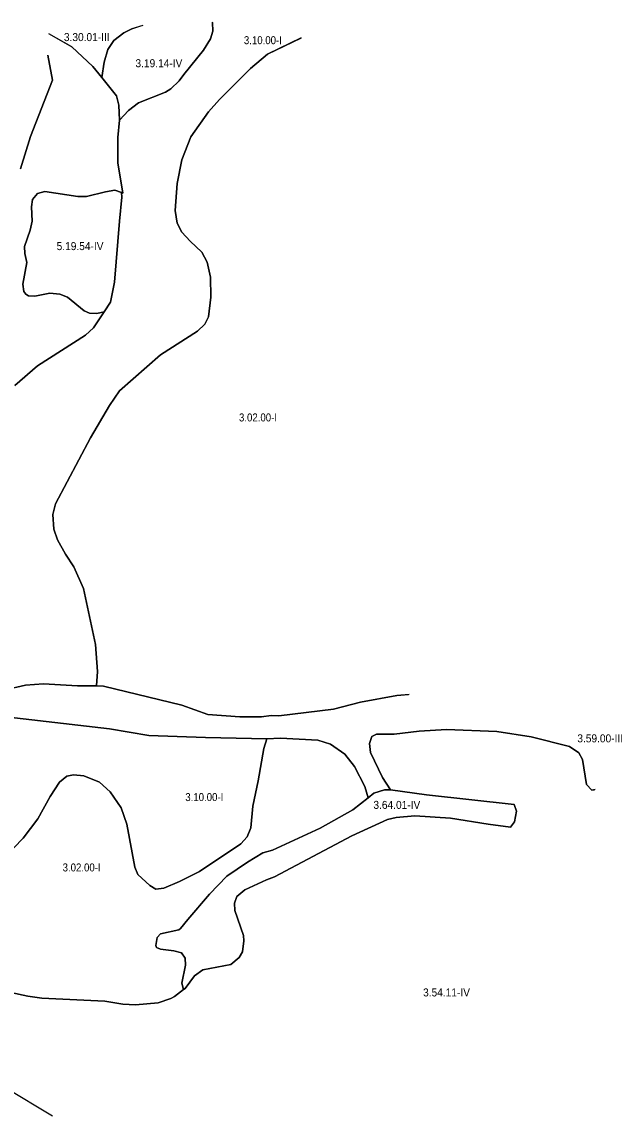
# Model space of a CAD drawing. Extents: x -589769 to -586623, y -1119592 to -1116833.
# Drawn here: x -588124 to -586623, y -1119592 to -1116859 of the extents above; entities that cross this region are included whole.
import ezdxf

# ---------------------------------------------------------------- set-up
doc = ezdxf.new("R2010")
doc.units = 0
doc.header["$LTSCALE"] = 8
doc.layers.add('40', color=7, linetype='Continuous', lineweight=25)
doc.layers.add('41', color=7, linetype='Continuous')

msp = doc.modelspace()

# ---------------------------------------------------------------- linework, layer by layer
at = {"layer": '40'}
for points in [[(-588141.5, -1117767), (-588085, -1117718), (-587964.5, -1117641.5), (-587944.5, -1117623.5), (-587918, -1117583), (-587902, -1117559), (-587892, -1117509.5), (-587880, -1117356.5), (-587873.5, -1117296.5), (-587875, -1117285.5), (-587871, -1117287), (-587883.5, -1117211), (-587883.5, -1117148), (-587880, -1117104.5), (-587857.5, -1117080), (-587832.5, -1117061), (-587765, -1117034.5), (-587751, -1117026), (-587730.5, -1117006), (-587719, -1116990.5), (-587669.5, -1116930), (-587652, -1116901), (-587646.5, -1116882), (-587647, -1116860.5)], [(-587648.116, -1116859.024), (-587647, -1116860.5), (-587646.5, -1116882), (-587652, -1116901), (-587669.5, -1116930), (-587719, -1116990.5), (-587730.5, -1117006), (-587751, -1117026), (-587765, -1117034.5), (-587832.5, -1117061), (-587857.5, -1117080), (-587880, -1117104.5), (-587881.5, -1117067), (-587887.5, -1117044), (-587924, -1116998), (-587918, -1116959.5), (-587909, -1116928), (-587894, -1116905.5), (-587868.5, -1116886), (-587849, -1116876.5), (-587828.645, -1116870.046)], [(-587821.559, -1116867.799), (-587849, -1116876.5), (-587868.5, -1116886), (-587894, -1116905.5), (-587909, -1116928), (-587918, -1116959.5), (-587924, -1116998), (-587946, -1116970.5), (-587998.5, -1116921), (-588056.201, -1116888.755)], [(-588055.306, -1116889.256), (-587998.5, -1116921), (-587946, -1116970.5), (-587924, -1116998)], [(-587425.916, -1116899.018), (-587510, -1116940), (-587552, -1116975.5), (-587629.5, -1117052.5), (-587657.5, -1117083.5), (-587701, -1117146), (-587723.5, -1117204), (-587735.5, -1117263), (-587740.5, -1117330.5), (-587735.5, -1117362), (-587724, -1117384.5), (-587703, -1117407), (-587673.5, -1117434), (-587660.5, -1117459), (-587652.5, -1117497), (-587651.5, -1117546.5), (-587657.5, -1117596), (-587666, -1117614), (-587684.5, -1117632), (-587777, -1117690.5), (-587880, -1117780.5), (-587904.5, -1117817), (-587952.5, -1117898), (-588040, -1118063), (-588046, -1118090), (-588043.5, -1118126), (-588034.5, -1118153), (-588015, -1118189)], [(-588040, -1118063), (-587952.5, -1117898), (-587904.5, -1117817), (-587880, -1117780.5), (-587777, -1117690.5), (-587684.5, -1117632), (-587666, -1117614), (-587657.5, -1117596), (-587651.5, -1117546.5), (-587652.5, -1117497), (-587660.5, -1117459), (-587673.5, -1117434), (-587703, -1117407), (-587724, -1117384.5), (-587735.5, -1117362), (-587740.5, -1117330.5), (-587735.5, -1117263), (-587723.5, -1117204), (-587701, -1117146), (-587657.5, -1117083.5), (-587629.5, -1117052.5), (-587552, -1116975.5), (-587510, -1116940), (-587425.003, -1116898.573)], [(-588058.91, -1116941.996), (-588047.5, -1117005), (-588102.5, -1117145.5), (-588127.5, -1117226.5)], [(-588127.5, -1117226.5), (-588102.5, -1117145.5), (-588047.5, -1117005), (-588058.91, -1116941.996), (-588058.91, -1116941.996)], [(-587924, -1116998), (-587887.5, -1117044), (-587881.5, -1117067), (-587880, -1117104.5), (-587883.5, -1117148), (-587883.5, -1117211), (-587871, -1117287), (-587875, -1117285.5), (-587891, -1117279.5), (-587915, -1117283.5), (-587962.5, -1117295.5), (-587983.5, -1117295.5), (-588066, -1117283), (-588084.5, -1117287.5), (-588097, -1117303), (-588100, -1117321), (-588098, -1117357), (-588103, -1117379.5), (-588117, -1117420), (-588116.5, -1117438), (-588111.5, -1117460.5), (-588121, -1117514.5), (-588118.5, -1117532.5), (-588113.5, -1117539.5), (-588107, -1117543), (-588091, -1117544.5), (-588054, -1117537), (-588029, -1117539), (-588010, -1117546.5), (-587968, -1117581), (-587954.5, -1117586.5), (-587936, -1117587.5), (-587918, -1117583), (-587944.5, -1117623.5), (-587964.5, -1117641.5), (-588085, -1117718), (-588141.5, -1117767)], [(-587155.542, -1118538.889), (-587186, -1118541.5), (-587277, -1118558.5), (-587345, -1118575.5), (-587481, -1118592.5), (-587500.5, -1118591.5), (-587525, -1118595), (-587578.5, -1118595), (-587658.5, -1118589), (-587724, -1118566), (-587919.5, -1118518.5), (-587937.5, -1118517.5), (-587934.5, -1118481.5), (-587939.5, -1118414), (-587970, -1118274.5), (-587994, -1118220.5), (-588015, -1118189), (-588034.5, -1118153), (-588043.5, -1118126), (-588046, -1118090), (-588040, -1118063)], [(-588015, -1118189), (-587994, -1118220.5), (-587970, -1118274.5), (-587939.5, -1118414), (-587934.5, -1118481.5), (-587937.5, -1118517.5), (-587984.5, -1118517.5), (-588070, -1118512.5), (-588114.5, -1118516), (-588165.5, -1118527.5)], [(-588165.5, -1118527.5), (-588114.5, -1118516), (-588070, -1118512.5), (-587984.5, -1118517.5), (-587937.5, -1118517.5), (-587919.5, -1118518.5), (-587724, -1118566), (-587658.5, -1118589), (-587578.5, -1118595), (-587525, -1118595), (-587500.5, -1118591.5), (-587481, -1118592.5), (-587345, -1118575.5), (-587277, -1118558.5), (-587186, -1118541.5), (-587157.521, -1118539.059)], [(-588178, -1118593), (-587905, -1118625), (-587806, -1118641.5), (-587664.5, -1118646.5), (-587511, -1118650), (-587518.5, -1118674), (-587533, -1118755), (-587546, -1118818), (-587551.5, -1118872), (-587560.5, -1118894.5), (-587576.5, -1118912.5), (-587679.5, -1118981.5), (-587729.5, -1119006.5), (-587768.5, -1119023), (-587788.5, -1119025.5), (-587804, -1119016), (-587834, -1118989), (-587841, -1118971), (-587861, -1118863), (-587875.5, -1118822.5), (-587903, -1118782), (-587929.5, -1118758.5), (-587969, -1118742.5), (-587995, -1118740), (-588011, -1118743), (-588029.5, -1118758), (-588053, -1118794), (-588083.5, -1118849.5), (-588120.5, -1118898), (-588190.5, -1118970)], [(-586690.345, -1118776.764), (-586699, -1118778), (-586712.5, -1118764.5), (-586722.5, -1118701.5), (-586731, -1118685), (-586755, -1118669), (-586850.5, -1118645), (-586936.5, -1118632), (-587062, -1118627), (-587130.5, -1118631), (-587193, -1118638), (-587237, -1118638.5), (-587249, -1118644.5), (-587254.5, -1118661.5), (-587252, -1118684), (-587222.5, -1118746.5), (-587202.5, -1118777), (-587217, -1118777.5), (-587243.5, -1118785.5), (-587258.381, -1118797.152), (-587266, -1118769), (-587292, -1118719.5), (-587316.5, -1118688), (-587352.5, -1118663.5), (-587384, -1118653.5), (-587477, -1118648), (-587511, -1118650), (-587664.5, -1118646.5), (-587806, -1118641.5), (-587905, -1118625), (-588178, -1118593)], [(-588151.702, -1119283.819), (-588109, -1119293), (-588074, -1119298), (-587916, -1119305), (-587871, -1119313), (-587840, -1119314.5), (-587783, -1119309.5), (-587751.5, -1119299), (-587742, -1119293.5), (-587719.491, -1119276.512), (-587715.5, -1119273.5), (-587692, -1119242), (-587671, -1119227), (-587601, -1119213.5), (-587580.5, -1119196), (-587572.5, -1119182), (-587569, -1119155), (-587570, -1119141.5), (-587591, -1119078.5), (-587592.5, -1119060.5), (-587586.5, -1119043.5), (-587566, -1119027), (-587512.5, -1119002), (-587492.5, -1118994.5), (-587298.5, -1118892), (-587209.5, -1118851.5), (-587188, -1118846.5), (-587141, -1118842), (-587052, -1118848), (-586958, -1118863), (-586902.5, -1118870.5), (-586892.5, -1118857.5), (-586887, -1118830.5), (-586893, -1118814), (-587112.5, -1118789.5), (-587202.5, -1118777), (-587222.5, -1118746.5), (-587252, -1118684), (-587254.5, -1118661.5), (-587249, -1118644.5), (-587237, -1118638.5), (-587193, -1118638), (-587130.5, -1118631), (-587062, -1118627), (-586936.5, -1118632), (-586850.5, -1118645), (-586755, -1118669), (-586731, -1118685)], [(-588190.5, -1118970), (-588120.5, -1118898), (-588083.5, -1118849.5), (-588053, -1118794), (-588029.5, -1118758), (-588011, -1118743), (-587995, -1118740), (-587969, -1118742.5), (-587929.5, -1118758.5), (-587903, -1118782), (-587875.5, -1118822.5), (-587861, -1118863), (-587841, -1118971), (-587834, -1118989), (-587804, -1119016), (-587788.5, -1119025.5), (-587768.5, -1119023), (-587729.5, -1119006.5), (-587679.5, -1118981.5), (-587576.5, -1118912.5), (-587560.5, -1118894.5), (-587551.5, -1118872), (-587546, -1118818), (-587533, -1118755), (-587518.5, -1118674), (-587511, -1118650), (-587477, -1118648), (-587384, -1118653.5), (-587352.5, -1118663.5), (-587316.5, -1118688), (-587292, -1118719.5), (-587266, -1118769), (-587258.381, -1118797.152), (-587296.5, -1118827), (-587378, -1118873), (-587497, -1118928.5), (-587521, -1118935), (-587560, -1118958), (-587611, -1118993), (-587655, -1119038), (-587709, -1119101), (-587727.5, -1119123.5), (-587731, -1119127), (-587777.5, -1119137), (-587785.5, -1119146), (-587789, -1119166.5), (-587787, -1119171), (-587777.5, -1119175.5), (-587744, -1119179.5), (-587724.5, -1119184.5), (-587715.5, -1119197.5), (-587715, -1119215.5), (-587723.5, -1119260), (-587719.491, -1119276.512), (-587742, -1119293.5), (-587751.5, -1119299), (-587783, -1119309.5), (-587840, -1119314.5), (-587871, -1119313), (-587916, -1119305), (-588074, -1119298), (-588109, -1119293), (-588151.702, -1119283.819)], [(-586731, -1118685), (-586722.5, -1118701.5), (-586712.5, -1118764.5), (-586699, -1118778), (-586692.368, -1118777.053)], [(-588047.479, -1119592.482), (-588166, -1119521)]]:
    msp.add_lwpolyline(points, dxfattribs=at)
for points in [[(-587875, -1117285.5), (-587873.5, -1117296.5), (-587880, -1117356.5), (-587892, -1117509.5), (-587902, -1117559), (-587918, -1117583), (-587936, -1117587.5), (-587954.5, -1117586.5), (-587968, -1117581), (-588010, -1117546.5), (-588029, -1117539), (-588054, -1117537), (-588091, -1117544.5), (-588107, -1117543), (-588113.5, -1117539.5), (-588118.5, -1117532.5), (-588121, -1117514.5), (-588111.5, -1117460.5), (-588116.5, -1117438), (-588117, -1117420), (-588103, -1117379.5), (-588098, -1117357), (-588100, -1117321), (-588097, -1117303), (-588084.5, -1117287.5), (-588066, -1117283), (-587983.5, -1117295.5), (-587962.5, -1117295.5), (-587915, -1117283.5), (-587891, -1117279.5)], [(-587719.491, -1119276.512), (-587723.5, -1119260), (-587715, -1119215.5), (-587715.5, -1119197.5), (-587724.5, -1119184.5), (-587744, -1119179.5), (-587777.5, -1119175.5), (-587787, -1119171), (-587789, -1119166.5), (-587785.5, -1119146), (-587777.5, -1119137), (-587731, -1119127), (-587727.5, -1119123.5), (-587709, -1119101), (-587655, -1119038), (-587611, -1118993), (-587560, -1118958), (-587521, -1118935), (-587497, -1118928.5), (-587378, -1118873), (-587296.5, -1118827), (-587258.381, -1118797.152), (-587243.5, -1118785.5), (-587217, -1118777.5), (-587202.5, -1118777), (-587112.5, -1118789.5), (-586893, -1118814), (-586887, -1118830.5), (-586892.5, -1118857.5), (-586902.5, -1118870.5), (-586958, -1118863), (-587052, -1118848), (-587141, -1118842), (-587188, -1118846.5), (-587209.5, -1118851.5), (-587298.5, -1118892), (-587492.5, -1118994.5), (-587512.5, -1119002), (-587566, -1119027), (-587586.5, -1119043.5), (-587592.5, -1119060.5), (-587591, -1119078.5), (-587570, -1119141.5), (-587569, -1119155), (-587572.5, -1119182), (-587580.5, -1119196), (-587601, -1119213.5), (-587671, -1119227), (-587692, -1119242), (-587715.5, -1119273.5)]]:
    msp.add_lwpolyline(points, close=True, dxfattribs=at)

# ---------------------------------------------------------------- texts
at = {"layer": '41'}
for s, width, p in [('3.30.01-III', 0.95, (-588018.753, -1116906.998)), ('3.10.00-I', 0.9, (-587568.75, -1116914.75)), ('3.19.14-IV', 0.95, (-587839.816, -1116972.25)), ('5.19.54-IV', 0.95, (-588036.943, -1117429.159)), ('3.02.00-I', 0.9, (-587580.986, -1117857.122)), ('3.59.00-III', 0.95, (-586735.178, -1118658.83)), ('3.10.00-I', 0.9, (-587715.25, -1118805.5)), ('3.64.01-IV', 0.95, (-587244.968, -1118825.015)), ('3.02.00-I', 0.9, (-588021.938, -1118981.25)), ('3.54.11-IV', 0.95, (-587120.75, -1119293.5))]:
    msp.add_text(s, height=20, dxfattribs=dict(at, width=width)).set_placement(p)

doc.saveas('drawing.dxf')
